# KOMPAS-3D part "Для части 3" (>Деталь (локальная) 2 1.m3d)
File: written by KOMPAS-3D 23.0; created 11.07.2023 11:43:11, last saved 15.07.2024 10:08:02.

Document properties: Автор: Владимир; Полное имя файла: C:\Users\YNA_NN\AppData\Local\Temp\KOMPAS-3D\ktf8-4528-2ed2-88cf\_Деталь (локальная) 2 1.m3d

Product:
- Body: Для части 3
    Материал: Сталь 3сп ГОСТ 380-2005 (density 7850 kg/m3)
    Масса: 141.3
- Part/product: Для части 3
    Материал: Сталь 3сп ГОСТ 380-2005 (density 7850 kg/m3)
    Масса: 141.3

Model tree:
1. Эскиз:1
2. Элемент выдавливания:3  (labels: Сталь 3сп ГОСТ 380-2005)
     Расстояние 1 = 100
